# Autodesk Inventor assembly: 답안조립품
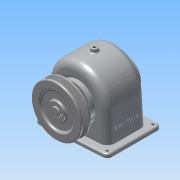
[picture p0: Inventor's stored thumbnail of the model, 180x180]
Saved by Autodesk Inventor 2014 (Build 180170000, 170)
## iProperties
Created: 2016-01
Part Number: 답안조립품
Document SubType Name: Assembly
Designer: User
Author: User
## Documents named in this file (16)
- C:\Documents and Settings\User\My Documents\Inventor\460106V1022\답안조립품.iam
- C:\Documents and Settings\User\My Documents\Inventor\460106V1022\본체.ipt
- C:\Documents and Settings\User\My Documents\Inventor\460106V1022\축.ipt
- C:\Documents and Settings\User\My Documents\Inventor\460106V1022\뒤커버.ipt
- C:\Documents and Settings\User\My Documents\Inventor\460106V1022\베어링 6203.ipt
- C:\Documents and Settings\User\My Documents\Inventor\460106V1022\오일씰 28 40 8.ipt
- C:\Documents and Settings\User\My Documents\Inventor\460106V1022\부시1.ipt
- C:\Documents and Settings\User\My Documents\Inventor\460106V1022\부시2.ipt
- C:\Documents and Settings\User\My Documents\Inventor\460106V1022\스퍼기어.ipt
- C:\Documents and Settings\User\My Documents\Inventor\460106V1022\키 - 6 x 6 x 22.ipt
- C:\Documents and Settings\User\My Documents\Inventor\460106V1022\키 - 5 x 5 x 18.ipt
- C:\Documents and Settings\User\My Documents\Inventor\460106V1022\앞커버.ipt
- C:\Documents and Settings\User\My Documents\Inventor\460106V1022\V-벨트풀리.ipt
- C:\Documents and Settings\User\My Documents\Inventor\460106V1022\멈춤나사 - M4x10.ipt
- C:\Documents and Settings\User\My Documents\Inventor\460106V1022\볼트 M3 x 10.ipt
- C:\Documents and Settings\User\My Documents\Inventor\460106V1022\볼트 M3 x 8.ipt
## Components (9 placed, 3 different names)
1. V-벨트풀리:1
2. ISO 4762 M3 x 8:1
3. ISO 4762 M3 x 10:1
4. ISO 4762 M3 x 8:2
5. ISO 4762 M3 x 10:2
6. ISO 4762 M3 x 8:3
7. ISO 4762 M3 x 10:3
8. ISO 4762 M3 x 8:4
9. ISO 4762 M3 x 10:4
